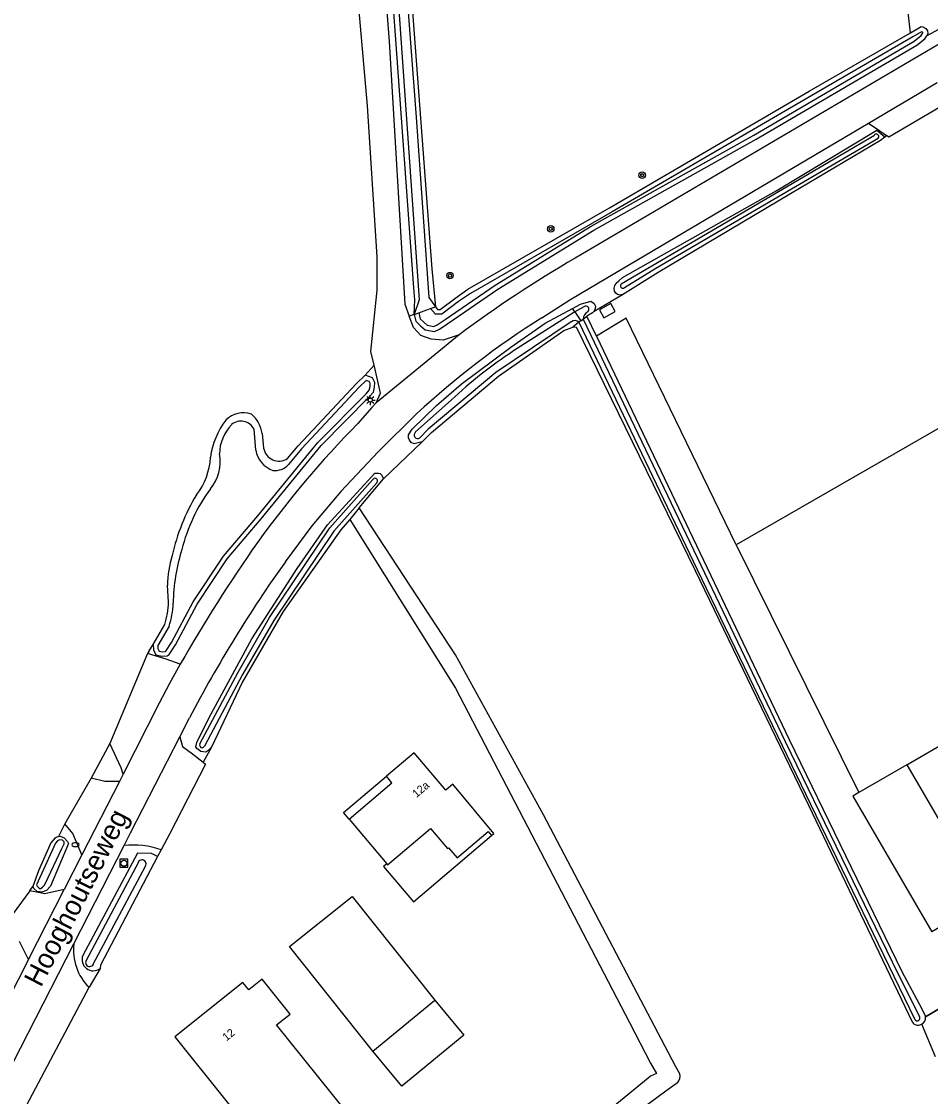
# Model space of a CAD drawing. Extents: x 141000 to 143000, y 400580 to 403500.
# Drawn here: x 141718.1 to 141831.6, y 403010.7 to 403145 of the extents above; entities that cross this region are included whole.
import ezdxf

# ---------------------------------------------------------------- set-up
doc = ezdxf.new("R2010")
doc.units = 0
for name, color, linetype in [('gg-afsc-erfafscheiding', 7, 'Continuous'), ('gg-afsc-hekwerk', 7, 'Continuous'), ('gg-anno-huisnummerreeks BGT', 7, 'Continuous'), ('gg-anno-openbare ruimte label', 7, 'Continuous'), ('gg-bbg-bassin', 7, 'Continuous'), ('gg-bbg-gedigitaliseerde bijgebouw', 7, 'Continuous'), ('gg-bbg-hoofdgebouw', 7, 'Continuous'), ('gg-bbg-luifel en loopbrug', 7, 'Continuous'), ('gg-bbg-open loods', 7, 'Continuous'), ('gg-knt-bronhoudergrens', 7, 'Continuous'), ('gg-knt-onverhard', 7, 'Continuous'), ('gg-knt-verharding', 7, 'Continuous'), ('gg-knt-verharding nz', 7, 'Continuous'), ('gg-kntw-bovenkant insteek waterloop', 7, 'Continuous'), ('gg-kntw-waterlijn', 7, 'Continuous'), ('gt-grn-vlakafsluiter', 7, 'Continuous'), ('gt-symb-boom', 7, 'Continuous'), ('gt-symb-brandkraan', 7, 'Continuous'), ('gt-symb-lichtmast', 7, 'Continuous'), ('gt-symb-rioolschacht', 7, 'Continuous')]:
    doc.layers.add(name, color=color, linetype=linetype)

# ---------------------------------------------------------------- blocks, each defined once
blk = doc.blocks.new('gt0-BOOM')
at = {"layer": 'gt-symb-boom'}
for radius in [0.4, 0.2]:
    blk.add_circle((0, 0), radius, dxfattribs=at)
blk = doc.blocks.new('gt0-LMAST')
at = {"layer": 'gt-symb-lichtmast'}
for p, q in [((-0.18, 0.17), (-0.45, 0.44)), ((-0.01, 0.25), (-0.01, 0.62)), ((0.17, 0.17), (0.44, 0.44)), ((-0.26, 0), (-0.63, 0)), ((-0.18, -0.18), (-0.45, -0.45)), ((-0.01, -0.25), (-0.01, -0.63)), ((0.44, -0.45), (0.17, -0.18)), ((0.24, 0), (0.62, 0))]:
    blk.add_line(p, q, dxfattribs=at)
blk.add_circle((-0.01, 0), 0.25, dxfattribs=at)
blk = doc.blocks.new('gt0-RS')
at = {"layer": 'gt-symb-rioolschacht'}
blk.add_lwpolyline([(-0.5, -0.5), (0.5, -0.5), (0.5, 0.5), (-0.5, 0.5)], close=True, dxfattribs=at)
blk.add_circle((0, 0), 0.375, dxfattribs=at)
blk = doc.blocks.new('gt0-BR')
at = {"layer": 'gt-symb-brandkraan'}
for centre, radius, start, end in [((-0.24, 0), 0.206, 107.5669, 252.4331), ((0.6, -2.66), 3, 106.892, 107.5669), ((0, -0.69), 0.938, 73.108, 106.892), ((-0.6, -2.66), 3, 72.4331, 73.108), ((0.24, 0), 0.206, 287.567, 72.4331), ((0.6, 2.66), 3, 252.4331, 253.108), ((0, 0.69), 0.938, 253.108, 286.8921), ((-0.6, 2.66), 3, 286.8921, 287.567)]:
    blk.add_arc(centre, radius, start, end, dxfattribs=at)

msp = doc.modelspace()

# ---------------------------------------------------------------- linework, layer by layer
at = {"layer": 'gg-afsc-erfafscheiding'}
for p, q in [((141833.1, 403144.23), (141831.19, 403143.2)), ((141825.92, 403130.59), (141826.14, 403130.74)), ((141789.62, 403108.8), (141793.16, 403110.89)), ((141767.12, 403108.39), (141766.51, 403108.16)), ((141761.01, 403100.79), (141762.12, 403102.04)), ((141733.96, 403066.26), (141734.51, 403067.14)), ((141733.96, 403066.26), (141733.8, 403066)), ((141729.08, 403054.77), (141726.77, 403050.42)), ((141741.81, 403054.32), (141740.77, 403052.44)), ((141723.49, 403044.75), (141722.69, 403043.15)), ((141735.51, 403041.49), (141735.07, 403040.67)), ((141719.1, 403036.35), (141719.46, 403036.9)), ((141727.88, 403026.67), (141726.5, 403024.32))]:
    msp.add_line(p, q, dxfattribs=at)
msp.add_lwpolyline([(141829.12, 403143.58), (141828.41, 403150.13), (141816.98, 403154.75), (141817.48, 403206.91), (141809.8, 403247.58), (141805.45, 403245.95), (141796.22, 403275.03)], dxfattribs=at)
at = {"layer": 'gg-afsc-hekwerk'}
msp.add_line((141886.23, 403053.07), (141831.02, 403020.63), dxfattribs=at)
at = {"layer": 'gg-bbg-bassin'}
msp.add_lwpolyline([(141792.25, 403108.77), (141791.69, 403109.76), (141790.27, 403108.97), (141790.83, 403107.97), (141792.25, 403108.77)], dxfattribs=at)
at = {"layer": 'gg-bbg-gedigitaliseerde bijgebouw'}
msp.add_line((141761.97, 403016.32), (141769.71, 403022.71), dxfattribs=at)
msp.add_lwpolyline([(141761.97, 403016.32), (141751.55, 403029.4), (141759.39, 403035.65), (141769.71, 403022.71)], dxfattribs=at)
at = {"layer": 'gg-bbg-hoofdgebouw'}
msp.add_line((141759, 403045.3), (141763.7, 403039.73), dxfattribs=at)
for points in [[(141776.79, 403043.28), (141777.09, 403043.54), (141771.97, 403049.7), (141771.07, 403048.95), (141767.14, 403053.61), (141763.66, 403050.67)], [(141759, 403045.3), (141764.35, 403049.85), (141763.66, 403050.67)], [(141763.7, 403039.73), (141763.79, 403039.62), (141769.18, 403044.16), (141771.3, 403041.65), (141771.41, 403041.75), (141772.49, 403040.47), (141776.39, 403043.76), (141776.79, 403043.28)], [(141748.15, 403025.34), (141746.46, 403023.98), (141745.7, 403024.93), (141737.21, 403018.13), (141749.95, 403002.22), (141757.49, 403007.88), (141758.62, 403008.79), (141749.94, 403019.62), (141751.64, 403020.97), (141748.15, 403025.34)]]:
    msp.add_lwpolyline(points, dxfattribs=at)
at = {"layer": 'gg-bbg-luifel en loopbrug'}
for points in [[(141759, 403045.3), (141758.31, 403046.14), (141763.66, 403050.67)], [(141763.7, 403039.73), (141763.29, 403039.4), (141767.02, 403034.98), (141776.79, 403043.28)], [(141769.71, 403022.71), (141773.32, 403018.32), (141765.59, 403011.94), (141761.97, 403016.32)]]:
    msp.add_lwpolyline(points, dxfattribs=at)
at = {"layer": 'gg-bbg-open loods'}
msp.add_line((141828.7, 403052.12), (141822.69, 403048.63), dxfattribs=at)
for points in [[(141828.7, 403052.12), (141838.56, 403035.18), (141831.81, 403031.25)], [(141822.69, 403048.63), (141821.95, 403048.2), (141831.81, 403031.25)]]:
    msp.add_lwpolyline(points, dxfattribs=at)
at = {"layer": 'gg-knt-bronhoudergrens'}
for p, q in [((141763.29, 403087.85), (141768.13, 403092.45)), ((141807.34, 403079.61), (141822.69, 403048.63)), ((141831.02, 403020.63), (141886.23, 403053.07))]:
    msp.add_line(p, q, dxfattribs=at)
for points in [[(141807.34, 403079.61), (141793.61, 403107.9), (141789.9, 403105.66)], [(141828.7, 403052.12), (141870.34, 403076.34), (141858.41, 403096.85), (141853.15, 403105.9), (141807.34, 403079.61)]]:
    msp.add_lwpolyline(points, dxfattribs=at)
at = {"layer": 'gg-knt-onverhard'}
msp.add_line((141832.25, 403015.61), (141830.54, 403019.7), dxfattribs=at)
at = {"layer": 'gg-knt-verharding'}
for p, q in [((141832.54, 403142.06), (141787.23, 403115.41)), ((141733.8, 403066), (141729.08, 403054.77)), ((141737.83, 403055.61), (141739.04, 403057.97)), ((141726.77, 403050.42), (141723.49, 403044.75)), ((141730.76, 403050.92), (141730.31, 403050.03)), ((141724.6, 403029.76), (141730.88, 403042.01)), ((141725.61, 403040.85), (141723.41, 403036.54)), ((141719.1, 403036.35), (141715.87, 403031.94)), ((141718.93, 403027.79), (141723.41, 403036.54)), ((141713.71, 403008.47), (141724.6, 403029.76)), ((141718.93, 403027.79), (141717.81, 403030.04)), ((141718.93, 403027.79), (141689.37, 402969.99)), ((141718.31, 403008.83), (141726.5, 403024.32))]:
    msp.add_line(p, q, dxfattribs=at)
for points in [[(141758.79, 403162.94), (141756.65, 403187.36), (141760.52, 403187.97), (141763.98, 403142.48), (141765.95, 403109.66), (141766.51, 403108.16)], [(141762.12, 403102.04), (141761.71, 403103.76), (141762.5, 403111.43), (141762.52, 403115.59), (141761.29, 403134.45), (141758.79, 403162.94)], [(141832.7, 403134.18), (141826.43, 403130.55), (141826.14, 403130.74)], [(141783.08, 403107.97), (141786.59, 403110.21), (141790.17, 403112.35), (141823.9, 403132.28)], [(141823.9, 403132.28), (141825.29, 403131.33), (141826.14, 403130.74)], [(141772.74, 403105.83), (141770.75, 403105.15), (141769.25, 403105.29), (141767.97, 403105.74), (141767.04, 403106.73), (141766.51, 403108.16)], [(141762.39, 403097.32), (141762.9, 403098.56), (141762.6, 403100.04), (141762.12, 403102.04)], [(141762.39, 403097.32), (141761.83, 403096.75), (141760.04, 403094.71)], [(141767.47, 403096), (141762.61, 403091.21), (141757.95, 403086.24), (141754.35, 403081.97), (141751.02, 403077.49)], [(141737.89, 403064.67), (141736.13, 403065.3), (141733.8, 403066)], [(141730.76, 403050.92), (141730.5, 403051.75), (141729.08, 403054.77)], [(141737.83, 403055.61), (141738.18, 403054.39), (141739.41, 403053.47), (141740.77, 403052.44)], [(141740.77, 403052.44), (141741.07, 403052.21), (141736.57, 403043.45), (141735.51, 403041.49)], [(141730.31, 403050.03), (141728.46, 403050.03), (141726.77, 403050.42)], [(141725.61, 403040.85), (141724.48, 403043.51), (141723.49, 403044.75)], [(141723.41, 403036.54), (141720.97, 403036), (141719.1, 403036.35)]]:
    msp.add_lwpolyline(points, dxfattribs=at)
for centre, radius, start, end in [((141863.59, 402984.17), 151.84, 120.192, 126.749), ((141840.7, 403016.67), 107.96, 122.2564, 132.7103), ((141853.45, 403003.29), 130.71, 135.6169, 144.1258), ((141893.97, 402976.31), 179.35, 144.7276, 150.4856), ((141890.24, 402978.62), 170.75, 144.6179, 152.3071), ((141732.1, 403032.13), 9.96, 69.9621, 97.0701), ((141731.05, 403028.95), 6.5, 172.8839, 225.515)]:
    msp.add_arc(centre, radius, start, end, dxfattribs=at)
at = {"layer": 'gg-knt-verharding nz'}
for p, q in [((141823.9, 403132.28), (141832.49, 403137.36)), ((141772.74, 403105.83), (141762.39, 403097.32)), ((141730.31, 403050.03), (141725.61, 403040.85))]:
    msp.add_line(p, q, dxfattribs=at)
for points in [[(141737.89, 403064.67), (141736.55, 403062.26), (141735.24, 403059.83), (141730.76, 403050.92)], [(141730.88, 403042.01), (141731.69, 403043.6), (141737.83, 403055.61)]]:
    msp.add_lwpolyline(points, dxfattribs=at)
at = {"layer": 'gg-kntw-bovenkant insteek waterloop'}
for p, q in [((141789.9, 403105.66), (141788.71, 403108.16)), ((141748.11, 403093.5), (141748.31, 403091.68)), ((141760.27, 403084.21), (141763.29, 403087.85)), ((141736.44, 403072.44), (141736.31, 403074.56)), ((141734.51, 403067.14), (141735.97, 403069.64))]:
    msp.add_line(p, q, dxfattribs=at)
for points in [[(141760.27, 403233.11), (141760.75, 403223.94), (141766.41, 403152.89), (141769.31, 403114.07), (141769.77, 403109.33)], [(141767.12, 403108.39), (141767.19, 403110.19), (141767.09, 403111.69), (141762.1, 403180.64), (141759.94, 403206.47), (141758, 403230.19), (141757.85, 403232.98)], [(141767.12, 403108.39), (141767.33, 403107.53), (141767.91, 403106.97), (141768.5, 403106.47), (141769.67, 403106.26), (141770.27, 403106.56), (141771.34, 403107.24), (141777.56, 403111.56), (141789.57, 403118.9), (141809.87, 403130.28), (141829.94, 403142.04), (141830.92, 403142.82), (141831.19, 403143.2)], [(141769.77, 403109.33), (141770.05, 403109), (141770.38, 403109.01), (141772.33, 403110.47), (141773.84, 403111.52), (141791.55, 403121.71), (141816.49, 403136.26), (141829.12, 403143.58)], [(141829.12, 403143.58), (141830.46, 403144.35), (141830.67, 403144.3), (141831.07, 403144.1), (141831.26, 403143.8), (141831.29, 403143.47), (141831.19, 403143.2)], [(141793.16, 403110.89), (141792.85, 403110.81), (141792.53, 403110.87), (141792.31, 403111.06), (141792.17, 403111.31), (141792.12, 403111.67), (141792.2, 403112.01), (141792.38, 403112.29), (141792.68, 403112.59), (141793.16, 403112.99), (141812.36, 403123.84), (141824.93, 403131.42), (141825.92, 403130.59)], [(141793.16, 403110.89), (141797.63, 403113.66), (141814.14, 403123.49), (141825.41, 403130.16), (141825.92, 403130.59)], [(141786.91, 403109.12), (141787.9, 403109.65), (141789.2, 403110.03), (141789.6, 403109.76), (141789.78, 403109.41), (141789.74, 403109.13), (141789.62, 403108.8)], [(141768.13, 403092.45), (141767.11, 403092.21), (141766.76, 403092.38), (141766.52, 403092.68), (141766.43, 403092.97), (141766.43, 403093.35), (141766.86, 403094.06), (141769.9, 403097.01), (141772.99, 403099.65), (141779.21, 403104.28), (141783.5, 403107.28), (141786.91, 403109.12)], [(141789.62, 403108.8), (141789.41, 403108.58), (141788.71, 403108.16)], [(141768.13, 403092.45), (141769.27, 403093.61), (141777.68, 403100.67), (141785.84, 403106.36), (141786.96, 403106.81)], [(141786.96, 403106.81), (141787.36, 403106.82), (141802.23, 403076.4), (141816.4, 403047.08), (141829.33, 403019.98)], [(141789.9, 403105.66), (141813.98, 403055.27), (141828.07, 403026.29), (141830.55, 403021.62), (141830.99, 403020.76), (141831.02, 403020.63)], [(141734.51, 403067.14), (141734.55, 403066.49), (141734.86, 403065.83), (141735.62, 403065.67), (141736.25, 403065.71), (141736.49, 403065.9), (141737.3, 403067.11), (141739.99, 403072.2), (141743.75, 403077.85), (141748.02, 403082.85), (141755.49, 403091.99), (141761.52, 403098.07), (141762.04, 403098.65), (141762.17, 403099.28), (141762.22, 403099.88), (141761.91, 403100.45), (141761.01, 403100.79)], [(141751.3, 403090.38), (141752.61, 403091.97), (141759.87, 403099.7), (141761.01, 403100.79)], [(141741.81, 403054.32), (141741.35, 403053.86), (141741.1, 403053.68), (141740.47, 403053.76), (141739.98, 403054.16), (141739.83, 403054.35), (141739.98, 403054.91), (141741.52, 403058.01), (141746.82, 403067.85), (141752.52, 403076.65), (141756.28, 403082.08), (141761.8, 403088.11), (141762.22, 403088.54), (141762.68, 403088.54), (141762.89, 403088.5), (141763.1, 403088.29), (141763.29, 403087.85)], [(141800.31, 403013.49), (141799.76, 403014.45), (141783.3, 403045.86), (141772.28, 403065.84), (141760.27, 403084.21)], [(141759.07, 403082.75), (141757.98, 403081.45), (141750.75, 403071.28), (141745.67, 403062.49), (141741.81, 403054.32)], [(141759.07, 403082.75), (141772.3, 403061.67), (141794.03, 403019.91), (141796.66, 403014.85), (141797.39, 403013.53), (141796.67, 403013.2), (141796.37, 403012.96), (141778.4, 402998.24)], [(141722.69, 403043.15), (141722.88, 403043.19), (141723.38, 403042.97), (141723.82, 403042.54), (141723.94, 403042.26), (141721.7, 403036.95), (141721.17, 403036.41), (141720.59, 403036.2), (141720.02, 403036.26), (141719.63, 403036.63), (141719.46, 403036.9)], [(141722.69, 403043.15), (141722.61, 403043.13), (141722.27, 403042.98), (141721.71, 403042.35), (141720.18, 403038.87), (141719.46, 403036.9)], [(141735.07, 403040.67), (141734.29, 403041.02), (141732.54, 403041.06), (141725.73, 403028.29)], [(141735.07, 403040.67), (141727.94, 403027.08), (141727.88, 403026.67)], [(141800.04, 403012.39), (141798.59, 403011.34), (141779.26, 402997.04)]]:
    msp.add_lwpolyline(points, dxfattribs=at)
for centre, radius, start, end in [((141745.75, 403093.08), 3.01, 69.9722, 135.7837), ((141751.2, 403089.3), 9.61, 142.3043, 172.6243), ((141744.28, 403092.97), 3.87, 7.9153, 49.5088), ((141750.23, 403092.01), 1.95, 189.6386, 303.3881), ((141733.4, 403090.95), 8.28, 321.8352, 357.1701), ((141761.13, 403073.04), 24.78, 148.9179, 167.8653), ((141747.78, 403074.61), 11.47, 161.5401, 180.2817), ((141724.7, 403072.97), 11.75, 343.5288, 357.3938), ((141727.01, 403027.76), 1.39, 157.3257, 308.5516), ((141830.09, 403020.52), 0.933, 215.5844, 263.4999), ((141830.09, 403020.52), 0.931, 263.3652, 284.3975), ((141830.09, 403020.53), 0.941, 284.3162, 298.2627), ((141830.09, 403020.52), 0.936, 298.2947, 6.5744), ((141799.09, 403013.21), 1.26, 319.3266, 12.7727)]:
    msp.add_arc(centre, radius, start, end, dxfattribs=at)
at = {"layer": 'gg-kntw-waterlijn'}
for p, q in [((141792.99, 403112.2), (141824.63, 403130.8)), ((141767.12, 403108.39), (141767.69, 403108.59)), ((141769.16, 403109.11), (141769.77, 403109.33)), ((141788.34, 403109.34), (141787.19, 403108.7)), ((141767.31, 403093.7), (141771.75, 403097.69)), ((141747.33, 403091.43), (141747.12, 403094.04)), ((141760.27, 403084.21), (141759.07, 403082.75)), ((141732.66, 403039.94), (141726.13, 403027.66)), ((141727.03, 403027.18), (141733.56, 403039.46))]:
    msp.add_line(p, q, dxfattribs=at)
for points in [[(141758.38, 403233.01), (141758.64, 403226.92), (141760.94, 403201.5), (141763.17, 403175.61), (141767.76, 403110.21), (141767.12, 403108.39)], [(141759.49, 403233.07), (141761.62, 403208.22), (141764.41, 403171.93), (141767.36, 403133.03), (141768.96, 403110.49), (141769.77, 403109.33)], [(141767.69, 403108.59), (141767.88, 403107.84), (141768.32, 403107.41), (141768.76, 403107.03), (141769.58, 403106.88), (141769.98, 403107.08), (141771.01, 403107.74), (141777.24, 403112.06), (141789.26, 403119.42), (141809.57, 403130.8), (141829.6, 403142.54), (141830.48, 403143.23), (141830.65, 403143.48), (141830.68, 403143.56), (141830.68, 403143.6), (141830.65, 403143.64), (141830.53, 403143.7), (141829.42, 403143.06), (141816.8, 403135.74), (141791.85, 403121.2), (141774.16, 403111.01), (141772.68, 403109.98), (141770.58, 403108.41), (141769.77, 403108.4), (141769.16, 403109.11)], [(141793.41, 403111.75), (141797.32, 403114.17), (141825.1, 403130.39)], [(141787.19, 403108.7), (141787.08, 403108.63), (141779.54, 403103.82)], [(141786.76, 403107.45), (141777.34, 403101.12), (141768.89, 403094.03), (141767.84, 403092.96)], [(141787.71, 403107.4), (141802.43, 403076.6), (141816.65, 403047.21), (141829.69, 403020.28)], [(141788.25, 403107.81), (141813.47, 403055.02), (141827.56, 403026.03), (141830.28, 403020.66)], [(141735.25, 403066.32), (141735.67, 403066.24), (141736.04, 403066.26), (141736.08, 403066.29), (141736.82, 403067.39), (141739.5, 403072.49), (141743.31, 403078.19), (141747.59, 403083.21), (141755.08, 403092.37), (141761.11, 403098.46), (141761.52, 403098.91), (141761.61, 403099.36), (141761.64, 403099.76), (141761.52, 403100), (141761.14, 403100.14), (141760.27, 403099.3), (141753.03, 403091.6), (141751.41, 403089.63)], [(141740.36, 403054.71), (141745.13, 403063.69), (141749.04, 403070.51), (141756.59, 403081.72), (141761.97, 403087.77)], [(141762.44, 403087.35), (141757.07, 403081.3), (141749.57, 403070.16), (141745.67, 403063.38), (141740.91, 403054.42)], [(141736.49, 403069.42), (141735.08, 403067), (141735.11, 403066.63), (141735.25, 403066.32)], [(141723.39, 403042.49), (141723.18, 403042.69), (141722.79, 403042.73), (141722.57, 403042.6), (141722.31, 403042.33), (141719.95, 403037.13), (141720.02, 403036.93), (141720.26, 403036.7), (141720.4, 403036.61), (141720.7, 403036.83), (141720.88, 403037.01), (141721.07, 403037.34), (141723.08, 403041.65), (141723.39, 403042.23), (141723.39, 403042.49)]]:
    msp.add_lwpolyline(points, dxfattribs=at)
for centre, radius, start, end in [((141824.87, 403130.6), 0.313, 317.2581, 139.08), ((141793.19, 403111.96), 0.305, 130.4185, 315.3295), ((141789.29, 403107.78), 1.05, 117.5144, 178.1758), ((141788.57, 403109.02), 0.395, 306.7539, 126.347), ((141787.21, 403106.89), 0.718, 44.8982, 128.6426), ((141810.33, 403056.68), 56.3, 123.154, 133.2597), ((141745.5, 403093.26), 1.8, 25.8421, 131.4047), ((141748.07, 403090.89), 5.28, 135.3659, 179.1278), ((141767.58, 403093.33), 0.455, 126.6783, 304.8213), ((141737.54, 403089.97), 5.35, 320.6687, 10.8047), ((141750.56, 403092), 3.29, 189.9883, 250.792), ((141749.74, 403091.11), 2.23, 263.3453, 318.4106), ((141762.22, 403087.59), 0.318, 312.9207, 143.8724), ((141759.08, 403073.74), 21.64, 143.592, 165.9475), ((141760.12, 403072.04), 23.1, 162.4796, 179.3599), ((141726.6, 403072.75), 10.44, 341.3882, 357.5191), ((141740.63, 403054.56), 0.313, 150.3428, 333.6629), ((141733.12, 403039.72), 0.512, 328.5697, 155.3909), ((141726.58, 403027.42), 0.511, 151.1872, 332.7734), ((141829.98, 403020.48), 0.351, 213.5554, 31.5622)]:
    msp.add_arc(centre, radius, start, end, dxfattribs=at)
at = {"layer": 'gt-grn-vlakafsluiter'}
for p, q in [((141787.19, 403108.7), (141786.91, 403109.12)), ((141787.19, 403108.7), (141787.94, 403107.57)), ((141787.71, 403107.4), (141786.96, 403106.81)), ((141787.94, 403107.57), (141787.71, 403107.4)), ((141787.94, 403107.57), (141788.25, 403107.81)), ((141788.25, 403107.81), (141788.71, 403108.16))]:
    msp.add_line(p, q, dxfattribs=at)
msp.add_lwpolyline([(141767.69, 403108.59), (141768.72, 403108.96), (141769.16, 403109.11)], dxfattribs=at)

# ---------------------------------------------------------------- block references
at = {"layer": 'gt-symb-boom'}
for p in [(141795.61, 403125.78), (141784.19, 403119.08), (141771.6, 403113.24)]:
    msp.add_blockref('gt0-BOOM', p, dxfattribs=at)
at = {"layer": 'gt-symb-brandkraan'}
msp.add_blockref('gt0-BR', (141724.81, 403042.13), dxfattribs=at)
at = {"layer": 'gt-symb-lichtmast'}
msp.add_blockref('gt0-LMAST', (141761.64, 403097.69), dxfattribs=at)
at = {"layer": 'gt-symb-rioolschacht'}
msp.add_blockref('gt0-RS', (141730.86, 403039.8), dxfattribs=at)

# ---------------------------------------------------------------- texts
at = {"layer": 'gg-anno-huisnummerreeks BGT'}
for s, rotation, p in [('12a', 40.1, (141767.41, 403047.95)), ('12', 38.7, (141743.66, 403017.53))]:
    msp.add_text(s, height=1, rotation=rotation, dxfattribs=at).set_placement(p)
at = {"layer": 'gg-anno-openbare ruimte label'}
msp.add_text('Hooghoutseweg', height=2.5, rotation=62.9, dxfattribs=at).set_placement((141720.49, 403024.21))

doc.saveas('drawing.dxf')
